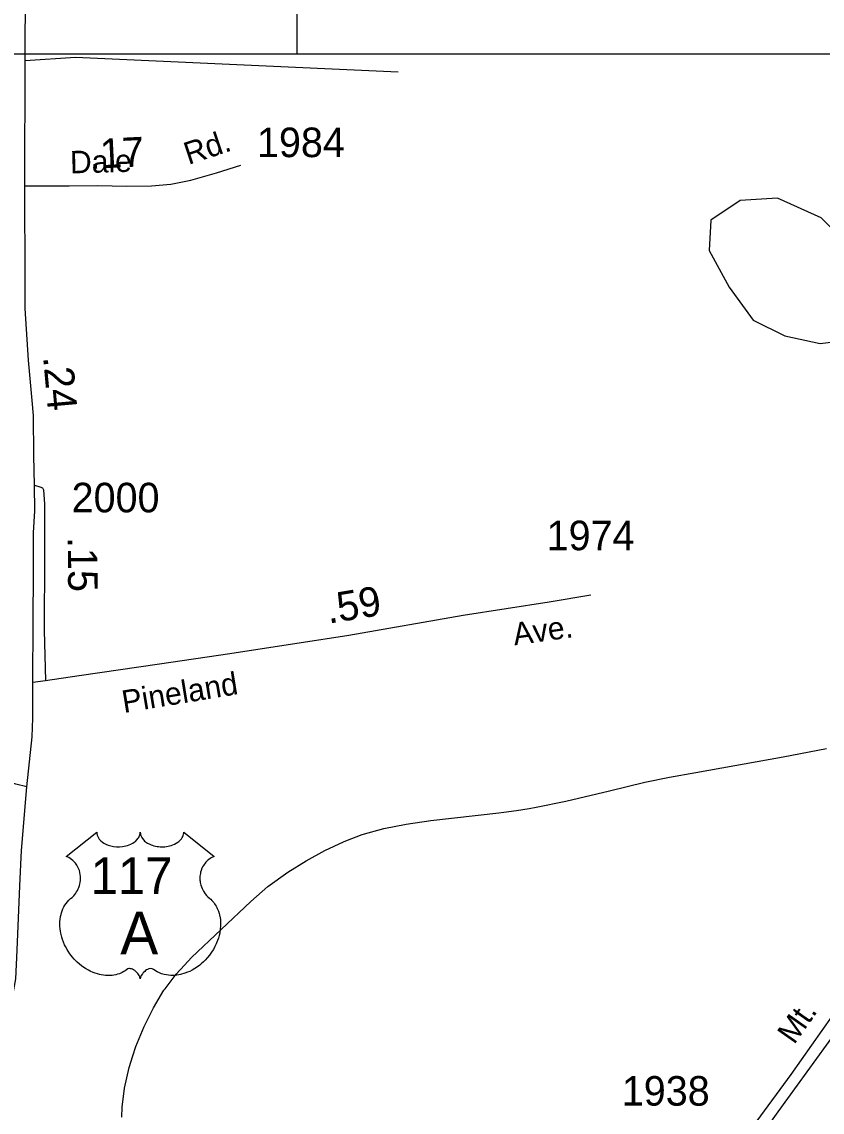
# Model space of a CAD drawing. Extents: x 2206922 to 2357709, y 510027 to 673830.
# Drawn here: x 2281670 to 2285056, y 535777 to 540388 of the extents above; entities that cross this region are included whole.
import ezdxf

# ---------------------------------------------------------------- set-up
doc = ezdxf.new("R2010")
doc.units = 0
for name, color, linetype in [('Exist Hydrographic Misc Water Feature', 7, 'Continuous'), ('Exist Hydrographic Pond Under 1500 Sq Ft', 7, 'Continuous'), ('Exist Railroad Mainline', 7, 'Continuous'), ('Exist Road Non-System Type 51', 7, 'Continuous'), ('Exist Road Primary US Attributed', 7, 'Continuous'), ('Exist Road Primary US Mileage Hundredths English Label', 7, 'Continuous'), ('Exist Road Primary US Shield CELL', 7, 'Continuous'), ('Exist Road Primary US Shield Number Label', 7, 'Continuous'), ('Exist Road Secondary Mileage Hundredths English Label', 7, 'Continuous'), ('Exist Road Secondary Type 51 Attributed', 7, 'Continuous'), ('Exist Road Secondary Type 51 Label', 7, 'Continuous'), ('Exist Road Secondary Type 51 Number Label', 7, 'Continuous'), ('Map Preparation Inset Cut Line', 7, 'Continuous')]:
    doc.layers.add(name, color=color, linetype=linetype)

msp = doc.modelspace()

# ---------------------------------------------------------------- linework, layer by layer
at = {"layer": 'Exist Hydrographic Misc Water Feature'}
for p, q in [((2284410, 537194.2), (2284520.7, 537214)), ((2283031, 536920.2), (2283040.3, 536923.8)), ((2282794.8, 536792.4), (2282872.9, 536839.9)), ((2282270.9, 536292.2), (2282276, 536299.1))]:
    msp.add_line(p, q, dxfattribs=at)
for points in [[(2284520.7, 537214), (2284889.8, 537280.1), (2285073.6, 537314.4)], [(2284520.7, 537214), (2284889.8, 537280.1), (2285073.6, 537314.4)], [(2284155.3, 537136.5), (2284305, 537172.4), (2284410, 537194.2)], [(2284155.3, 537136.5), (2284305, 537172.4), (2284410, 537194.2)], [(2283815.4, 537061.5), (2283844.9, 537066.5), (2283971.2, 537092.5), (2284155.3, 537136.5)], [(2283815.4, 537061.5), (2283844.9, 537066.5), (2283971.2, 537092.5), (2284155.3, 537136.5)], [(2283040.3, 536923.8), (2283109, 536950.7), (2283200.8, 536977), (2283295.8, 536995.5), (2283399.7, 537010.2), (2283687, 537043.1), (2283708.1, 537045.8)], [(2283040.3, 536923.8), (2283109, 536950.7), (2283200.8, 536977), (2283295.8, 536995.5), (2283399.7, 537010.2), (2283687, 537043.1), (2283708.1, 537045.8)], [(2283708.1, 537045.8), (2283762.2, 537052.6), (2283815.4, 537061.5)], [(2283708.1, 537045.8), (2283762.2, 537052.6), (2283815.4, 537061.5)], [(2282872.9, 536839.9), (2282950.9, 536882.9), (2283031, 536920.2)], [(2282872.9, 536839.9), (2282950.9, 536882.9), (2283031, 536920.2)], [(2282638.2, 536668), (2282710.7, 536732), (2282794.8, 536792.4)], [(2282638.2, 536668), (2282710.7, 536732), (2282794.8, 536792.4)], [(2282357.8, 536398.8), (2282387.8, 536431.2), (2282638.2, 536668)], [(2282357.8, 536398.8), (2282387.8, 536431.2), (2282638.2, 536668)], [(2282276, 536299.1), (2282323, 536361), (2282357.8, 536398.8)], [(2282276, 536299.1), (2282323, 536361), (2282357.8, 536398.8)], [(2282203.9, 536173.6), (2282226, 536218.6), (2282270.9, 536292.2)], [(2282203.9, 536173.6), (2282226, 536218.6), (2282270.9, 536292.2)], [(2282139.5, 536015.1), (2282152, 536054.1), (2282187, 536139.4), (2282203.9, 536173.6)], [(2282139.5, 536015.1), (2282152, 536054.1), (2282187, 536139.4), (2282203.9, 536173.6)], [(2282092.9, 535756.4), (2282093.7, 535798.3), (2282103.8, 535879.1), (2282123.9, 535966.1), (2282139.5, 536015.1)], [(2282092.9, 535756.4), (2282093.7, 535798.3), (2282103.8, 535879.1), (2282123.9, 535966.1), (2282139.5, 536015.1)]]:
    msp.add_lwpolyline(points, dxfattribs=at)
at = {"layer": 'Exist Hydrographic Pond Under 1500 Sq Ft'}
msp.add_lwpolyline([(2285046.9, 539028.4), (2285114, 539036.9), (2285238, 539119.7), (2285279, 539220.4), (2285218.9, 539388.9), (2285051, 539559.6), (2284866.9, 539642), (2284709, 539632.1), (2284584.9, 539549.3), (2284576.9, 539421.5), (2284662, 539265.7), (2284762.9, 539126), (2284897, 539060.9), (2285046.9, 539028.4)], dxfattribs=at)
at = {"layer": 'Exist Railroad Mainline'}
msp.add_lwpolyline([(2285970.5, 537863.7), (2285956.5, 537803.4), (2285921.6, 537687.1), (2285890.8, 537566.8), (2285824.4, 537406.4), (2285759.6, 537259.8), (2285665.8, 537047.2), (2285565.6, 536858.3), (2285457.6, 536655.3), (2285313.9, 536412.1), (2285112.9, 536116.5), (2284868.2, 535778.3), (2284743.9, 535605.3), (2284140, 534774), (2284110.5, 534734.3)], dxfattribs=at)
at = {"layer": 'Exist Road Non-System Type 51'}
msp.add_lwpolyline([(2281683.5, 540225.5), (2281896.2, 540238.8), (2283261.6, 540176.7)], dxfattribs=at)
at = {"layer": 'Exist Road Primary US Attributed'}
for points in [[(2281681.8, 539695), (2281683.5, 540225.5), (2281683.7, 540252.9), (2281686.8, 540763.6), (2281690.1, 541265.3), (2281700.1, 541969.9), (2281703.4, 542216), (2281706.8, 542440.4), (2281706.8, 542566.8), (2281713.4, 542669.9), (2281716.7, 542731.4), (2281718.4, 542788), (2281730, 542856.2)], [(2281723.3, 538428.9), (2281720, 538554.3), (2281718.4, 538723.9), (2281713.4, 538787.1), (2281697.9, 538956.7), (2281683.5, 539176.2), (2281683.5, 539289.3), (2281681.8, 539695)], [(2281716.7, 537595.1), (2281717.4, 537849.3), (2281719.1, 538061.9), (2281719.1, 538226.8), (2281724.3, 538319.8), (2281723.3, 538428.9)], [(2281691.1, 537152.6), (2281713.9, 537364.4), (2281716, 537443.7), (2281716.7, 537595.1)], [(2281196.6, 535499.5), (2281261.8, 535584.6), (2281356.7, 535703), (2281455.9, 535837.9), (2281496.6, 535905.3), (2281530.9, 535971.4), (2281570.3, 536064.3), (2281607.2, 536174.9), (2281627.4, 536247.6), (2281644, 536341.5), (2281650.4, 536462.3), (2281660.6, 536734.5), (2281668.5, 536883.1), (2281691.1, 537152.6)]]:
    msp.add_lwpolyline(points, dxfattribs=at)
at = {"layer": 'Exist Road Primary US Shield CELL'}
msp.add_lwpolyline([(2281986.5, 536960.6), (2281986.8, 536955.3), (2281988.1, 536949), (2281989.1, 536945.8), (2281992.1, 536939.5), (2281996.9, 536932.1), (2282003.7, 536924.9), (2282011.4, 536918.6), (2282016.5, 536915.3), (2282025.3, 536910.6), (2282035.3, 536906.4), (2282046.4, 536903.2), (2282057.7, 536900.9), (2282070.1, 536899.5), (2282082.3, 536899.3), (2282095.5, 536900.3), (2282110.1, 536903.1), (2282116.8, 536904.9), (2282124.4, 536907.5), (2282131.3, 536910.3), (2282139, 536914.4), (2282145.2, 536918.4), (2282150, 536921.9), (2282156.8, 536928.4), (2282162.3, 536935.2), (2282164.5, 536939), (2282166.5, 536942.6), (2282169.2, 536950.4), (2282170, 536953.8), (2282170.5, 536960.9), (2282171, 536954.9), (2282171.6, 536951.2), (2282172.5, 536947.6), (2282174.1, 536943.7), (2282176.8, 536938.2), (2282179.8, 536933.7), (2282185.6, 536926.9), (2282189.1, 536923.6), (2282192.4, 536920.9), (2282201.1, 536914.9), (2282211.4, 536909.7), (2282216.4, 536907.5), (2282221.5, 536905.7), (2282228.1, 536903.7), (2282234.8, 536902.1), (2282241.5, 536901), (2282248.3, 536900), (2282255.3, 536899.5), (2282261, 536899.3), (2282268, 536899.4), (2282274.5, 536899.8), (2282281.1, 536900.5), (2282288.4, 536901.8), (2282294.2, 536903), (2282302, 536905.1), (2282309, 536907.6), (2282315.1, 536910.3), (2282323.1, 536914.4), (2282329.5, 536918.5), (2282334.2, 536922.3), (2282339.9, 536927.4), (2282345.2, 536933.6), (2282348.3, 536938.1), (2282350.5, 536942.7), (2282352.5, 536947.6), (2282353.8, 536952.7), (2282354.4, 536957.2), (2282354.5, 536961.1), (2282483.1, 536858.6), (2282480.1, 536857.5), (2282473.1, 536854), (2282467.6, 536850.8), (2282458.7, 536844.5), (2282454.9, 536841.1), (2282451.1, 536837.5), (2282447.6, 536833.7), (2282444.6, 536830.2), (2282440.8, 536825), (2282437.5, 536819.8), (2282434.2, 536814.1), (2282431.8, 536809.2), (2282427.9, 536798.9), (2282426, 536792.3), (2282424.8, 536786.8), (2282423.3, 536775.3), (2282422.9, 536769.8), (2282422.9, 536764.4), (2282423.2, 536758.7), (2282423.7, 536753.3), (2282424.7, 536747.6), (2282425.6, 536742.6), (2282427.2, 536736.4), (2282429.5, 536729.3), (2282432.3, 536722.3), (2282438.2, 536711.2), (2282445.7, 536699.8), (2282451.1, 536693.4), (2282456.4, 536687.9), (2282464.4, 536681.2), (2282468.7, 536677.4), (2282473.6, 536672.5), (2282481.7, 536663.2), (2282484.9, 536658.7), (2282488.2, 536653.8), (2282491.3, 536648.7), (2282494.3, 536643.2), (2282496.7, 536638.5), (2282501.2, 536627.4), (2282504.5, 536616.7), (2282506.1, 536611.1), (2282508.5, 536598.5), (2282509.4, 536592.3), (2282510.4, 536579.9), (2282510.4, 536565.1), (2282509.3, 536550.9), (2282506.6, 536534.4), (2282504.4, 536524.6), (2282501, 536513.1), (2282497.8, 536503.1), (2282491.9, 536488.5), (2282486.7, 536477.8), (2282479.9, 536465.4), (2282475.3, 536457.8), (2282469.9, 536449.8), (2282463.1, 536440.5), (2282455.2, 536430.6), (2282445.7, 536420.2), (2282438.1, 536412.5), (2282428, 536403.6), (2282422, 536398.6), (2282413.3, 536392), (2282401.5, 536384.1), (2282389.8, 536377.4), (2282379.8, 536372.3), (2282371, 536368.5), (2282359.6, 536364.1), (2282340.6, 536358.9), (2282333.7, 536357.5), (2282325.5, 536356.2), (2282317.8, 536355.5), (2282310.4, 536355), (2282300.4, 536355), (2282290.4, 536355.8), (2282281, 536357.2), (2282271.2, 536359.2), (2282261, 536362.2), (2282251.6, 536365.9), (2282242.2, 536370.5), (2282226.3, 536380.6), (2282221.7, 536383), (2282219.1, 536383.7), (2282213, 536384), (2282207.2, 536382.8), (2282201.3, 536380.4), (2282197.7, 536378.5), (2282193, 536375.4), (2282189.3, 536372.5), (2282184.9, 536368.3), (2282181.9, 536364.8), (2282179.6, 536362.1), (2282175.1, 536355), (2282173.5, 536351.7), (2282171.8, 536347.3), (2282170.4, 536341), (2282168.3, 536349), (2282166, 536354.3), (2282163.2, 536358.9), (2282160.4, 536362.9), (2282155.9, 536368.1), (2282151.9, 536372), (2282147, 536375.9), (2282141.9, 536379), (2282137.7, 536381.2), (2282133.9, 536382.6), (2282129.3, 536383.7), (2282125.5, 536384.1), (2282122.4, 536384), (2282118.1, 536383), (2282112.3, 536378.8), (2282106.8, 536375), (2282100.8, 536371.3), (2282093.6, 536367.5), (2282088.4, 536365.1), (2282082.2, 536362.6), (2282074.9, 536360.2), (2282067, 536358.1), (2282058.9, 536356.5), (2282051.7, 536355.4), (2282044, 536354.7), (2282037.1, 536354.5), (2282029.9, 536354.6), (2282023.2, 536355.1), (2282015.3, 536355.8), (2282005.6, 536357.2), (2281997.6, 536359.1), (2281989.1, 536361.3), (2281980.3, 536364.1), (2281971, 536367.6), (2281959.3, 536372.7), (2281951.2, 536376.9), (2281938.3, 536384.3), (2281923.3, 536394.7), (2281911.9, 536403.9), (2281903.6, 536411.4), (2281891.4, 536423.9), (2281884.2, 536432), (2281872.9, 536446.6), (2281865.7, 536457.2), (2281861.1, 536464.9), (2281854.2, 536477.4), (2281850.5, 536485.2), (2281845.6, 536496.6), (2281841.8, 536507), (2281838.6, 536516.9), (2281836.9, 536523.2), (2281834.4, 536534.2), (2281833, 536542), (2281831.5, 536552.7), (2281830.7, 536564.1), (2281830.6, 536574.5), (2281830.8, 536583.1), (2281831.8, 536593.2), (2281833.5, 536604), (2281835.6, 536613.1), (2281837.4, 536619.8), (2281840.2, 536627.8), (2281843.8, 536636.7), (2281848, 536645.2), (2281852.1, 536652.3), (2281857.2, 536659.9), (2281862.2, 536666.3), (2281868.8, 536673.5), (2281875.6, 536680), (2281881.9, 536685.1), (2281889.3, 536692.4), (2281893.2, 536696.8), (2281897.9, 536703), (2281901.6, 536708.7), (2281904.5, 536713.8), (2281908.5, 536721.3), (2281910.8, 536726.9), (2281913.8, 536735.6), (2281915.2, 536741.6), (2281916.8, 536749.5), (2281917.8, 536756.8), (2281918.1, 536766), (2281917.9, 536773.6), (2281916.9, 536782.5), (2281915.2, 536791), (2281913.2, 536798.5), (2281910, 536807), (2281907.1, 536813.2), (2281902.2, 536821.7), (2281896.7, 536829.5), (2281891.1, 536835.9), (2281885.4, 536841.6), (2281879.9, 536845.8), (2281874.7, 536849.5), (2281868.2, 536853.5), (2281861.9, 536856.6), (2281857.9, 536858.2)], close=True, dxfattribs=at)
at = {"layer": 'Exist Road Secondary Type 51 Attributed'}
msp.add_line((2281716.7, 537595.1), (2281770.1, 537602.7), dxfattribs=at)
for points in [[(2281681.8, 539695), (2281869.6, 539695), (2281989.3, 539696.7), (2282113.9, 539693.4), (2282218.6, 539695), (2282300.1, 539701.7), (2282384.8, 539718.3), (2282492.9, 539749.9), (2282595.9, 539781.5)], [(2281723.3, 538428.9), (2281745.2, 538422.3), (2281756.8, 538418.1), (2281762, 538409.3), (2281765.6, 538348.8), (2281765.6, 538129.5), (2281764.7, 537814.1), (2281770.1, 537602.7)], [(2281770.1, 537602.7), (2281912.8, 537623.1), (2282251.9, 537673), (2282549.4, 537716.2), (2283052.4, 537793.7), (2283537.3, 537878.3), (2283900.5, 537935.8), (2284076.3, 537965.2)], [(2284052.9, 534755.5), (2284113.4, 534833.7), (2284291.2, 535065.2), (2284470.7, 535318.9), (2284621.1, 535523.8), (2284923.6, 535935.8), (2285099, 536183.8), (2285240.1, 536396.2), (2285435.9, 536733.2), (2285556.6, 536981.3), (2285659.6, 537210.2), (2285761.3, 537473.5), (2285841.4, 537697.3), (2285885.9, 537843.6)], [(2281691.1, 537152.6), (2281643.6, 537164.1), (2281608.7, 537175.8), (2281585.4, 537187.4), (2281568.8, 537202.4), (2281548.9, 537222.3), (2281499, 537273.9), (2281432.5, 537340.4)]]:
    msp.add_lwpolyline(points, dxfattribs=at)
at = {"layer": 'Map Preparation Inset Cut Line'}
for points in [[(2282834.5, 540252.9), (2282834.5, 546746.4), (2271763.2, 546746.4), (2271763.2, 540252.9)], [(2282834.5, 540252.9), (2289054.2, 540252.9), (2289054.2, 521583.5), (2268884.2, 521583.5)], [(2271763.2, 540252.9), (2282834.5, 540252.9)]]:
    msp.add_lwpolyline(points, dxfattribs=at)

# ---------------------------------------------------------------- texts
at = {"layer": 'Exist Road Primary US Mileage Hundredths English Label'}
msp.add_text('.24', height=125, rotation=275.209, dxfattribs=at).set_placement((2281759.4, 538970.8))
at = {"layer": 'Exist Road Primary US Shield Number Label'}
for s, height, p in [('117', 155, (2281960.9, 536699.3)), ('A', 180, (2282086.1, 536444.5))]:
    msp.add_text(s, height=height, dxfattribs=at).set_placement(p)
at = {"layer": 'Exist Road Secondary Mileage Hundredths English Label'}
for s, rotation, p in [('.17', 2.8624, (2281957.3, 539766.1)), ('.15', 270.5571, (2281863.7, 538209)), ('.59', 9.4107, (2282967.3, 537842.7))]:
    msp.add_text(s, height=125, rotation=rotation, dxfattribs=at).set_placement(p)
at = {"layer": 'Exist Road Secondary Type 51 Label'}
for s, rotation, p in [('Rd.', 18.4902, (2282374.5, 539782.6)), ('Dale', 1.6047, (2281874.7, 539747.1)), ('Ave.', 7.9866, (2283753.8, 537750.9)), ('Pineland', 9.4107, (2282101.3, 537464.9)), ('Mt.', 54.942, (2284936.9, 536059.7))]:
    msp.add_text(s, height=95, rotation=rotation, dxfattribs=at).set_placement(p)
at = {"layer": 'Exist Road Secondary Type 51 Number Label'}
for s, p in [('1984', (2282664.4, 539816.1)), ('2000', (2281880.3, 538313.9)), ('1974', (2283889.7, 538153.5)), ('1938', (2284207.7, 535804.5))]:
    msp.add_text(s, height=125, dxfattribs=at).set_placement(p)

doc.saveas('drawing.dxf')
